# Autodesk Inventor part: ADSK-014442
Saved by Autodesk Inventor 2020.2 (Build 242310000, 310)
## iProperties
Part Number: ADSK-014442
Material: Allgemein
Description: Framegenerator-Skeleton-Referenz
Document SubType Name: Modellieren
Designer: lutzd
Density: 1 g/cm^3
Appearance: Vorgabe
_SkeletonDoc: Frame Skeleton File
_Version: 15.0.0
Title: Gestellrahmenbauteil(e)
Author: lutzd
Revision Number: -
DocNumber: ADSK-014442
Folder: .
Mass: 0 kg
VLT_Material: Generisch
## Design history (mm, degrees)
sketch "Referenzrahmen"
node "Volumenkörper"
node "Flächenkörper"
